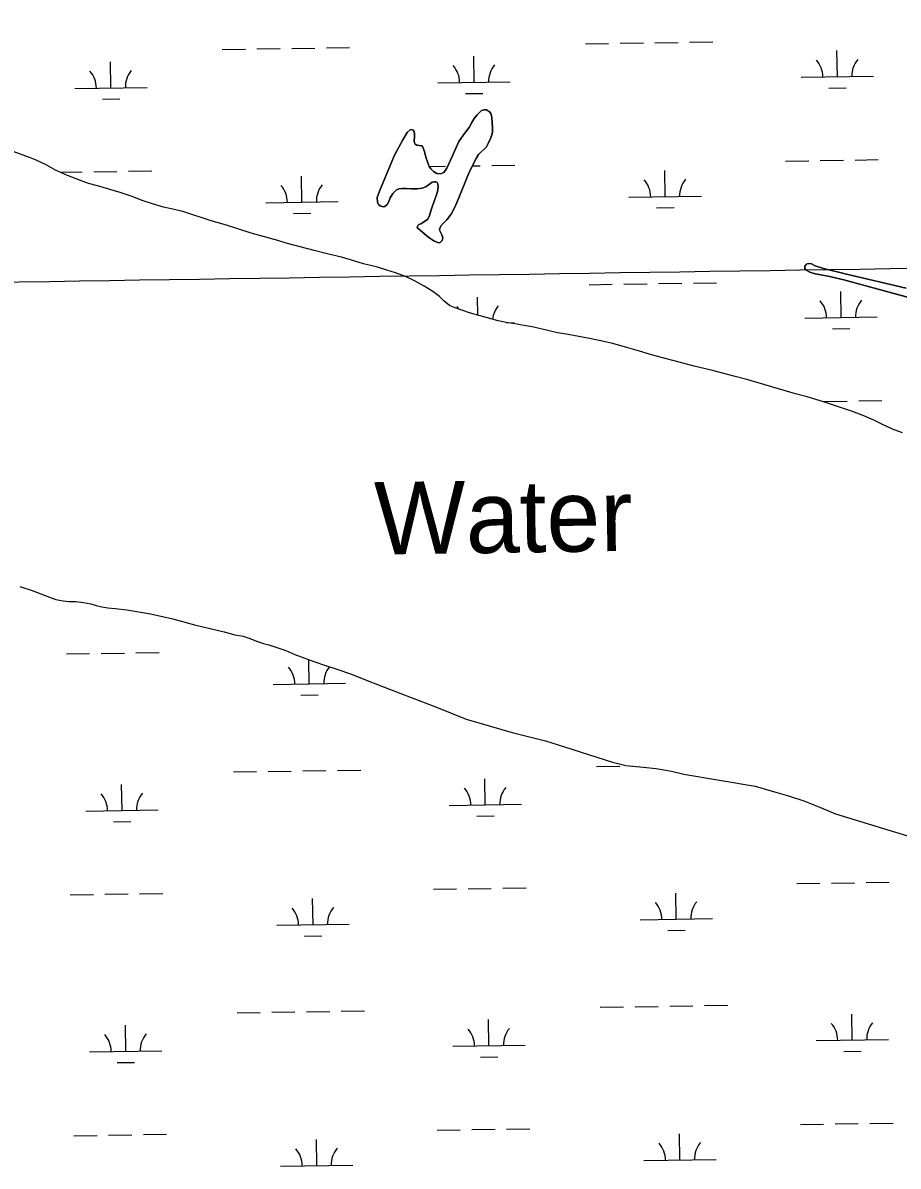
# Model space of a CAD drawing. Extents: x 3823584 to 3861785, y 301729 to 327625.
# Drawn here: x 3836481 to 3837691, y 318188 to 319767 of the extents above; entities that cross this region are included whole.
import ezdxf

# ---------------------------------------------------------------- set-up
doc = ezdxf.new("R2010")
doc.units = 0
for name, color, linetype in [('V-GRID-MAJR', 7, 'Continuous'), ('V-RIVR-IDEN', 7, 'Continuous'), ('V-TOPO-SHOR', 7, 'Continuous'), ('V-WETL-SWMP', 7, 'Continuous')]:
    doc.layers.add(name, color=color, linetype=linetype)

msp = doc.modelspace()

# ---------------------------------------------------------------- linework, layer by layer
at = {"layer": 'V-GRID-MAJR'}
msp.add_spline([(3827642.978, 319275.864), (3832951.406, 319355.783), (3838259.823, 319436.473), (3843568.228, 319517.936), (3848876.6210000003, 319600.17), (3854185.002, 319683.177), (3859493.3710000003, 319766.956), (3859493.372, 319766.956)], degree=3, dxfattribs=at)
at = {"layer": 'V-TOPO-SHOR'}
for points in [[(3837096.325, 319556.064), (3837083.596, 319525.401), (3837078.384, 319512.288), (3837073.092, 319502.832), (3837067.018, 319494.96), (3837059.364, 319487.098), (3837057.466, 319483.553), (3837057.054, 319480.886), (3837058.129, 319478.607), (3837060.4760000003, 319474.244), (3837061.441, 319470.18700000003), (3837060.728, 319466.435), (3837058.142, 319463.48600000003), (3837055.768, 319463.105), (3837049.36, 319465.907), (3837042.173, 319470.59500000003), (3837034.207, 319477.261), (3837027.323, 319483.329), (3837026.342, 319484.718), (3837027.444, 319487.38), (3837028.6380000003, 319488.658), (3837031.114, 319489.631), (3837034.881, 319491.587), (3837040.836, 319496), (3837043.234, 319500.729), (3837045.454, 319508.62200000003), (3837047.463, 319514.244), (3837053.3880000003, 319530.913), (3837054.701, 319535.944), (3837055.127, 319541.179), (3837054.75, 319544.444), (3837053.8740000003, 319546.424), (3837052.002, 319547.62), (3837049.7290000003, 319547.634), (3837046.759, 319546.762), (3837043.286, 319544.014), (3837038.323, 319540.684), (3837032.878, 319538.738), (3837026.054, 319537.689), (3837018.544, 319537.732), (3837011.529, 319538.169), (3837005.895, 319538.3), (3837001.052, 319537.833), (3836996.988, 319535.879), (3836992.417, 319531.359), (3836989.022, 319525.35000000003), (3836987.115, 319520.42100000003), (3836984.721, 319516.284), (3836981.739, 319513.435), (3836979.068, 319513.054), (3836975.1240000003, 319514.363), (3836972.761, 319515.956), (3836971.296, 319519.126), (3836971.038, 319525.94800000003), (3836974.9560000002, 319536.79600000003), (3836995.092, 319584.412), (3837006.2800000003, 319605.398), (3837012.467, 319615.741), (3837016.539, 319619.175), (3837018.419, 319619.462), (3837020.786, 319618.954), (3837021.767, 319617.563), (3837022.636, 319614.002), (3837022.5130000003, 319609.752), (3837022.185, 319604.221), (3837022.365, 319601.255), (3837023.541, 319599.369), (3837025.708, 319598.271), (3837029.0640000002, 319597.757), (3837032.6180000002, 319596.946), (3837034.19, 319595.259), (3837036.328, 319589.217), (3837037.967, 319581.697), (3837042.929, 319568.426), (3837045.282, 319565.151), (3837048.92, 319561.57300000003), (3837053.5500000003, 319559.077), (3837058.586, 319558.552), (3837063.145, 319560.406), (3837067.0300000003, 319566.114), (3837074.733, 319582.377), (3837083.9420000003, 319603.076), (3837089.128, 319610.854), (3837093.1070000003, 319615.87200000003), (3837097.99, 319622.663), (3837101.883, 319629.559), (3837105.076, 319634.777), (3837108.86, 319639.895), (3837115.1210000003, 319645.98600000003), (3837118.98, 319646.854), (3837121.7460000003, 319646.737), (3837125.9820000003, 319644.14400000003), (3837127.845, 319641.95900000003), (3837129.4, 319636.911), (3837129.85, 319629.397), (3837130.1, 319621.59), (3837130.274, 319617.142), (3837129.758, 319613.586), (3837128.048, 319608.063), (3837124.446, 319600.27400000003), (3837121.753, 319595.943)], [(3837121.753, 319595.943), (3837118.5700000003, 319592.404), (3837114.398, 319588.869), (3837111.117, 319585.232), (3837108.324, 319580.701), (3837100.3310000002, 319565.43), (3837096.325, 319556.064)], [(3836996.179, 319421.957), (3836984.342, 319425.58400000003), (3836971.223, 319429.512), (3836952.176, 319434.364), (3836938.561, 319438.39400000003), (3836921.4930000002, 319443.23600000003), (3836901.953, 319447.794), (3836883.994, 319452.443), (3836845.119, 319462.84500000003), (3836833.576, 319466.272), (3836815.224, 319471.318), (3836796.872, 319476.362), (3836778.227, 319482.301), (3836762.941, 319487.427), (3836741.433, 319493.58), (3836702.568, 319506.253), (3836692.899, 319508.78), (3836675.923, 319512.534), (3836660.3340000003, 319516.97000000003), (3836647.413, 319521.391), (3836631.046, 319527.515), (3836615.757, 319532.739), (3836584.4820000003, 319541.714), (3836571.953, 319545.244), (3836560.9080000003, 319549.261), (3836543.258, 319556.181), (3836526.3030000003, 319563.59), (3836513.4990000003, 319570.978), (3836499.798, 319577.183), (3836490.629, 319580.99), (3836467.947, 319589.322)], [(3837696.847, 319200.935), (3837682.843, 319205.954), (3837669.242, 319212.358), (3837657.219, 319218.058), (3837643.517, 319224.067), (3837627.74, 319230.088), (3837587.597, 319243.56), (3837564.807, 319250.31), (3837548.9220000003, 319254.75), (3837481.441, 319274.505), (3837461.8030000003, 319279.36100000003), (3837436.051, 319286.424), (3837409.11, 319292.806), (3837350.105, 319308.559), (3837333.432, 319313.49700000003), (3837317.251, 319318.136), (3837296.433, 319323.987), (3837277.681, 319328.245), (3837264.3570000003, 319331.087), (3837234.642, 319336.594), (3837220.2290000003, 319339.048), (3837204.733, 319342.398), (3837185.194, 319347.055), (3837171.472, 319349.605), (3837161.105, 319351.344), (3837149.157, 319352.995), (3837137.9050000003, 319355.626), (3837113.438, 319362.29), (3837100.019, 319366.221), (3837087.887, 319370.044), (3837080.096, 319372.856), (3837074.771, 319374.863), (3837070.63, 319376.665), (3837063.548, 319382.537), (3837057.163, 319389.097), (3837047.715, 319395.869), (3837035.997, 319403.25), (3837023.488, 319410.339), (3837010.083, 319416.64), (3836996.179, 319421.957)], [(3837712.136, 319385.742), (3837645.83, 319403.711), (3837615.8370000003, 319412.284), (3837593.827, 319417.054), (3837576.157, 319420.319), (3837568.661, 319422.831), (3837563.8340000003, 319425.33), (3837561.968, 319427.51300000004), (3837561.886, 319430.776), (3837564.1780000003, 319433.925), (3837566.1580000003, 319434.505), (3837570.998, 319434.083), (3837576.122, 319431.288), (3837587.662, 319427.564), (3837619.437, 319419.87200000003), (3837701.646, 319400.33)], [(3836477.356, 318988.53), (3836494.123, 318982.999), (3836518.2830000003, 318973.869), (3836527.061, 318970.754), (3836536.932, 318968.821), (3836544.534, 318967.887), (3836554.514, 318967.63300000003), (3836565.082, 318966.48600000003), (3836575.25, 318964.45), (3836582.846, 318962.33), (3836590.444, 318960.51), (3836598.738, 318959.176), (3836609.1070000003, 318957.931), (3836625.109, 318956.457), (3836657.588, 318950.737), (3836688.578, 318943.93700000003), (3836718.772, 318935.762), (3836759.332, 318926.042), (3836774.33, 318922.003), (3836785.977, 318919.76300000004), (3836796.235, 318916.443), (3836804.419, 318913.13300000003), (3836813.789, 318910.016), (3836821.286, 318907.8), (3836832.532, 318904.376), (3836844.7630000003, 318900.05700000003), (3836857.182, 318894.451), (3836883.3140000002, 318884.816), (3836899.688, 318879.384), (3836915.1750000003, 318874.354), (3836935.295, 318867.52), (3836956.887, 318858.8), (3837002.344, 318841.443), (3837052.7290000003, 318821.686)], [(3837052.7290000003, 318821.686), (3837094.096, 318805.12), (3837157.324, 318786.919), (3837203.343, 318775.434), (3837229.541, 318767.211), (3837295.964, 318745.871), (3837314.4760000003, 318741.28), (3837338.2490000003, 318738.842), (3837356.21, 318737.147), (3837377.353, 318733.368), (3837394.804, 318729.559), (3837493.123, 318712.712), (3837523.017, 318703.994), (3837539.42, 318699.382), (3837560.328, 318692.435), (3837583.364, 318683.393), (3837604.288, 318674.597), (3837703.512, 318644.299)]]:
    msp.add_lwpolyline(points, dxfattribs=at)
at = {"layer": 'V-WETL-SWMP'}
for p, q in [((3837258.679514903, 319737.9917449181), (3837290.675711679, 319738.48508539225)), ((3837306.673810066, 319738.73175562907), (3837338.670006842, 319739.22509610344)), ((3837354.6681052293, 319739.4717663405), (3837386.664302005, 319739.96510681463)), ((3837402.662400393, 319740.2117770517), (3837434.658597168, 319740.70511752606)), ((3836756.8311670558, 319730.2538845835), (3836788.827363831, 319730.7472250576)), ((3836804.8254622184, 319730.99389529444), (3836836.8216589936, 319731.4872357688)), ((3836852.8197573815, 319731.73390600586), (3836884.815954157, 319732.22724648)), ((3836900.8140525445, 319732.47391671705), (3836932.81024932, 319732.9672571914)), ((3837104.8881740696, 319684.8724536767), (3837104.3331646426, 319720.8681708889)), ((3837606.736521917, 319692.61031401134), (3837606.18151249, 319728.60603122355)), ((3836603.0398262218, 319677.1345933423), (3836602.4848167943, 319713.1303105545)), ((3837556.742464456, 319691.83946952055), (3837656.7305793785, 319693.38115850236)), ((3836553.0457687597, 319676.3637488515), (3836653.0338836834, 319677.90543783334)), ((3837054.894116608, 319684.1016091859), (3837154.882231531, 319685.64329816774)), ((3837594.97584675, 319676.9961471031), (3837618.9729943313, 319677.36615245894)), ((3836591.2791510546, 319661.52042643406), (3836615.2762986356, 319661.89043178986)), ((3837093.1274989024, 319669.25828676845), (3837117.1246464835, 319669.62829212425)), ((3837042.912999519, 319568.47116892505), (3837065.2647023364, 319568.81580362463)), ((3837102.402600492, 319569.3884225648), (3837113.2589974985, 319569.5558143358)), ((3837129.2570958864, 319569.80248457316), (3837161.2532926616, 319570.295825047)), ((3837368.7885170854, 319527.0602398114), (3837368.233507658, 319563.05595702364)), ((3837535.116853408, 319576.0603234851), (3837567.1130501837, 319576.55366395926)), ((3837583.111148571, 319576.8003341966), (3837615.1073453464, 319577.29367467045)), ((3837631.105443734, 319577.5403449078), (3837663.10164051, 319578.03368538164)), ((3836533.1215502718, 319560.6108361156), (3836563.4163544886, 319561.07794329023)), ((3836579.4144528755, 319561.32461352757), (3836611.4106496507, 319561.8179540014)), ((3836627.4087480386, 319562.06462423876), (3836659.404944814, 319562.5579647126)), ((3836866.940169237, 319519.3223794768), (3836866.38515981, 319555.318096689)), ((3836816.946111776, 319518.5515349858), (3836916.934226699, 319520.0932239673)), ((3837318.7944596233, 319526.2893953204), (3837418.7825745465, 319527.8310843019)), ((3836855.1794940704, 319503.7082125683), (3836879.176641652, 319504.0782179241)), ((3837357.027841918, 319511.44607290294), (3837381.0249894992, 319511.81607825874)), ((3837263.808341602, 319405.356322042), (3837295.8045383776, 319405.84966251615)), ((3837311.8026367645, 319406.09633275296), (3837343.79883354, 319406.58967322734)), ((3837359.7969319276, 319406.8363434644), (3837391.7931287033, 319407.32968393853)), ((3837407.791227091, 319407.5763541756), (3837439.7874238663, 319408.06969464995)), ((3837611.8653486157, 319359.97489113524), (3837611.3103391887, 319395.97060834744)), ((3837109.845779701, 319363.3417522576), (3837109.461991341, 319388.2327480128)), ((3837561.871291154, 319359.20404664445), (3837661.8594060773, 319360.7457356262)), ((3837150.1557543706, 319352.85591909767), (3837160.0110582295, 319353.0078752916)), ((3837600.1046734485, 319344.360724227), (3837624.1018210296, 319344.7307295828)), ((3837588.23997527, 319244.16491132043), (3837620.2361720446, 319244.65825179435)), ((3837636.2342704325, 319244.9049220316), (3837668.230467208, 319245.39826250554)), ((3836541.6778111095, 318895.3137570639), (3836573.674007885, 318895.807097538)), ((3836589.672106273, 318896.0537677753), (3836621.6683030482, 318896.5471082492)), ((3836637.666401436, 318896.7937784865), (3836669.6625982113, 318897.2871189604)), ((3836877.197822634, 318854.05153372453), (3836876.685795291, 318887.2596029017)), ((3836827.203765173, 318853.28068923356), (3836927.1918800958, 318854.8223782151)), ((3836865.437147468, 318838.43736681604), (3836889.434295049, 318838.8073721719)), ((3836772.217647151, 318732.3476159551), (3836804.2138439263, 318732.84095642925)), ((3836820.211942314, 318733.08762666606), (3836852.20813909, 318733.58096714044)), ((3836868.2062374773, 318733.8276373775), (3836900.202434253, 318734.32097785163)), ((3836916.2005326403, 318734.5676480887), (3836948.196729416, 318735.06098856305)), ((3837274.065994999, 318740.08547628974), (3837306.0621917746, 318740.5788167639)), ((3836618.426306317, 318679.22832471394), (3836617.87129689, 318715.22404192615)), ((3837120.274654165, 318686.96618504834), (3837119.719644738, 318722.96190226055)), ((3836568.4322488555, 318678.4574802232), (3836668.4203637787, 318679.99916920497)), ((3837070.2805967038, 318686.1953405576), (3837170.2687116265, 318687.73702953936)), ((3836606.6656311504, 318663.6141578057), (3836630.6627787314, 318663.98416316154)), ((3837108.513978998, 318671.3520181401), (3837132.5111265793, 318671.72202349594)), ((3837048.654985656, 318570.4161945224), (3837080.6511824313, 318570.9095349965)), ((3837096.649280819, 318571.1562052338), (3837128.6454775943, 318571.6495457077)), ((3837144.643575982, 318571.896215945), (3837176.6397727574, 318572.38955641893)), ((3837550.503333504, 318578.15405485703), (3837582.499530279, 318578.6473953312)), ((3837598.497628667, 318578.89406556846), (3837630.4938254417, 318579.38740604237)), ((3837646.4919238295, 318579.63407627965), (3837678.4881206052, 318580.12741675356)), ((3836546.8066378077, 318562.678334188), (3836578.8028345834, 318563.1716746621)), ((3836594.8009329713, 318563.41834489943), (3836626.7971297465, 318563.9116853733)), ((3836642.7952281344, 318564.1583556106), (3836674.7914249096, 318564.65169608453)), ((3836882.3266493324, 318521.41611084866), (3836881.7716399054, 318557.41182806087)), ((3837384.1749971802, 318529.1539711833), (3837383.619987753, 318565.1496883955)), ((3836832.3325918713, 318520.6452663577), (3836932.320706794, 318522.1869553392)), ((3837334.180939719, 318528.3831266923), (3837434.169054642, 318529.92481567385)), ((3836870.565974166, 318505.80194394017), (3836894.563121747, 318506.171949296)), ((3837372.4143220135, 318513.5398042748), (3837396.411469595, 318513.90980963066)), ((3836777.3464738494, 318399.71219307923), (3836809.3426706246, 318400.2055335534)), ((3836825.3407690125, 318400.4522037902), (3836857.336965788, 318400.94554426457)), ((3836873.3350641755, 318401.1922145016), (3836905.3312609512, 318401.68555497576)), ((3836921.3293593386, 318401.9322252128), (3836953.3255561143, 318402.4255656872)), ((3837279.194821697, 318407.45005341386), (3837311.191018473, 318407.943393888)), ((3837327.1891168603, 318408.1900641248), (3837359.185313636, 318408.6834045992)), ((3837375.183412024, 318408.93007483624), (3837407.179608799, 318409.4234153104)), ((3837423.177707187, 318409.67008554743), (3837455.1739039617, 318410.1634260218)), ((3837627.2518287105, 318362.0686225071), (3837626.6968192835, 318398.0643397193)), ((3836623.5551330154, 318346.59290183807), (3836623.0001235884, 318382.5886190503)), ((3837125.403480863, 318354.33076217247), (3837124.848471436, 318390.3264793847)), ((3836573.5610755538, 318345.8220573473), (3836673.549190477, 318347.3637463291)), ((3837075.409423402, 318353.5599176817), (3837175.397538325, 318355.1016066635)), ((3837577.2577712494, 318361.29777801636), (3837677.245886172, 318362.8394669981)), ((3837113.6428056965, 318338.7165952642), (3837137.6399532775, 318339.08660062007)), ((3837615.491153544, 318346.45445559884), (3837639.488301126, 318346.8244609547)), ((3836611.7944578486, 318330.9787349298), (3836635.7916054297, 318331.34874028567)), ((3837053.7838123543, 318237.78077164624), (3837085.78000913, 318238.2741121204)), ((3837101.7781075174, 318238.5207823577), (3837133.7743042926, 318239.0141228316)), ((3837149.7724026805, 318239.2607930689), (3837181.7685994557, 318239.75413354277)), ((3837555.632160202, 318245.5186319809), (3837587.6283569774, 318246.011972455)), ((3837603.626455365, 318246.25864269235), (3837635.622652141, 318246.7519831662)), ((3837651.6207505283, 318246.99865340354), (3837683.616947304, 318247.4919938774)), ((3836551.935464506, 318230.04291131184), (3836583.931661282, 318230.536251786)), ((3836599.9297596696, 318230.7829220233), (3836631.925956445, 318231.2762624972)), ((3836647.9240548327, 318231.5229327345), (3836679.920251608, 318232.01627320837)), ((3836887.455476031, 318188.78068797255), (3836886.900466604, 318224.77640518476)), ((3837389.303823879, 318196.5185483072), (3837388.748814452, 318232.5142655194)), ((3836837.4614185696, 318188.00984348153), (3836937.449533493, 318189.55153246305)), ((3837339.3097664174, 318195.74770381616), (3837439.29788134, 318197.28939279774))]:
    msp.add_line(p, q, dxfattribs=at)
for points in [[(3837121.752, 319595.942), (3837124.4450000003, 319600.275), (3837128.048, 319608.06200000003), (3837129.759, 319613.586), (3837130.274, 319617.141), (3837130.1010000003, 319621.589), (3837129.85, 319629.397), (3837129.399, 319636.911), (3837127.846, 319641.96), (3837125.981, 319644.14400000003), (3837121.747, 319646.738), (3837118.98, 319646.853), (3837115.1210000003, 319645.985), (3837108.86, 319639.89400000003), (3837105.076, 319634.777), (3837101.883, 319629.558), (3837097.99, 319622.662), (3837093.108, 319615.871), (3837089.127, 319610.854), (3837083.943, 319603.076), (3837074.733, 319582.376), (3837067.0300000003, 319566.114), (3837063.144, 319560.405), (3837058.5870000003, 319558.553), (3837053.5500000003, 319559.076), (3837048.919, 319561.57300000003), (3837045.2830000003, 319565.151), (3837042.93, 319568.426), (3837037.966, 319581.697), (3837036.329, 319589.217), (3837034.19, 319595.25800000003), (3837032.6180000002, 319596.947), (3837029.065, 319597.75800000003), (3837025.708, 319598.271), (3837023.54, 319599.37), (3837022.365, 319601.255), (3837022.184, 319604.221), (3837022.5130000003, 319609.753), (3837022.636, 319614.002), (3837021.767, 319617.564), (3837020.786, 319618.953), (3837018.418, 319619.461), (3837016.538, 319619.175), (3837012.467, 319615.74), (3837006.2800000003, 319605.39900000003), (3836995.092, 319584.413), (3836974.9560000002, 319536.79600000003), (3836971.039, 319525.94800000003), (3836971.2970000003, 319519.127), (3836972.761, 319515.957), (3836975.1240000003, 319514.362), (3836979.069, 319513.055), (3836981.74, 319513.435), (3836984.721, 319516.284), (3836987.116, 319520.42), (3836989.022, 319525.351), (3836992.417, 319531.36), (3836996.988, 319535.879), (3837001.051, 319537.833), (3837005.896, 319538.299), (3837011.529, 319538.168), (3837018.543, 319537.733), (3837026.0530000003, 319537.69), (3837032.878, 319538.738), (3837038.324, 319540.683), (3837043.285, 319544.014), (3837046.759, 319546.762), (3837049.7290000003, 319547.634), (3837052.002, 319547.621), (3837053.873, 319546.424), (3837054.751, 319544.443), (3837055.128, 319541.18), (3837054.702, 319535.944), (3837053.389, 319530.912), (3837047.463, 319514.244), (3837045.454, 319508.623), (3837043.235, 319500.73), (3837040.836, 319496), (3837034.881, 319491.587), (3837031.115, 319489.632), (3837028.6380000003, 319488.658), (3837027.4450000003, 319487.38), (3837026.343, 319484.718), (3837027.323, 319483.329), (3837034.2060000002, 319477.261), (3837042.173, 319470.594), (3837049.36, 319465.908), (3837055.768, 319463.105), (3837058.142, 319463.48600000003), (3837060.728, 319466.436), (3837061.441, 319470.18700000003), (3837060.4760000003, 319474.245), (3837058.129, 319478.606), (3837057.055, 319480.886), (3837057.466, 319483.552), (3837059.364, 319487.098), (3837067.018, 319494.96), (3837073.092, 319502.832), (3837078.384, 319512.289), (3837083.597, 319525.402), (3837096.324, 319556.064)], [(3837096.324, 319556.064), (3837100.33, 319565.429), (3837108.324, 319580.701), (3837111.117, 319585.231), (3837114.399, 319588.869), (3837118.5700000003, 319592.403), (3837121.752, 319595.942)], [(3837080.096, 319372.857), (3837074.771, 319374.864), (3837070.63, 319376.666), (3837063.549, 319382.537), (3837057.163, 319389.096), (3837047.715, 319395.87), (3837035.997, 319403.25), (3837023.487, 319410.338), (3837010.0840000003, 319416.64), (3836996.18, 319421.957), (3836984.342, 319425.583), (3836971.222, 319429.512), (3836952.177, 319434.364), (3836938.562, 319438.395), (3836921.494, 319443.23600000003), (3836901.953, 319447.795), (3836883.994, 319452.444), (3836845.1180000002, 319462.84500000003), (3836833.576, 319466.271), (3836815.224, 319471.317), (3836796.872, 319476.363), (3836778.228, 319482.301), (3836762.94, 319487.428), (3836741.432, 319493.579), (3836702.569, 319506.253), (3836692.899, 319508.779), (3836675.923, 319512.533), (3836660.335, 319516.97000000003), (3836647.414, 319521.392), (3836631.045, 319527.514), (3836615.757, 319532.74), (3836584.4820000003, 319541.714), (3836571.952, 319545.245), (3836560.907, 319549.261), (3836543.258, 319556.181), (3836526.3030000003, 319563.591), (3836513.498, 319570.977), (3836499.7970000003, 319577.18200000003), (3836490.629, 319580.99), (3836467.947, 319589.322)], [(3837701.645, 319400.329), (3837619.438, 319419.87200000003), (3837587.662, 319427.565), (3837576.1210000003, 319431.287), (3837570.998, 319434.083), (3837566.1580000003, 319434.506), (3837564.1780000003, 319433.925), (3837561.887, 319430.776), (3837561.968, 319427.514), (3837563.833, 319425.329), (3837568.661, 319422.831), (3837576.157, 319420.318), (3837593.827, 319417.054), (3837615.8370000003, 319412.284), (3837645.83, 319403.712), (3837712.1350000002, 319385.742)], [(3837696.847, 319200.934), (3837682.843, 319205.955), (3837669.242, 319212.358), (3837657.218, 319218.059), (3837643.517, 319224.067), (3837627.739, 319230.087), (3837587.596, 319243.559), (3837564.807, 319250.31), (3837548.9220000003, 319254.749), (3837481.441, 319274.505), (3837461.8030000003, 319279.36), (3837436.051, 319286.425), (3837409.109, 319292.805), (3837350.1040000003, 319308.559), (3837333.431, 319313.49700000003), (3837317.251, 319318.135), (3837296.433, 319323.98600000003), (3837277.681, 319328.244), (3837264.3570000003, 319331.087), (3837234.643, 319336.594), (3837220.2290000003, 319339.048), (3837204.733, 319342.398), (3837185.193, 319347.056), (3837171.471, 319349.605), (3837161.105, 319351.344), (3837149.157, 319352.994), (3837137.906, 319355.627), (3837113.437, 319362.29), (3837100.02, 319366.22000000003), (3837087.886, 319370.045), (3837080.096, 319372.857)], [(3836477.355, 318988.53), (3836494.123, 318982.999), (3836518.282, 318973.868), (3836527.06, 318970.754), (3836536.931, 318968.82), (3836544.535, 318967.887), (3836554.514, 318967.632), (3836565.082, 318966.485), (3836575.2490000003, 318964.45), (3836582.846, 318962.331), (3836590.4450000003, 318960.509), (3836598.738, 318959.177), (3836609.1070000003, 318957.93200000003), (3836625.108, 318956.457), (3836657.588, 318950.737), (3836688.579, 318943.938), (3836718.771, 318935.761), (3836759.332, 318926.042), (3836774.329, 318922.003), (3836785.977, 318919.762), (3836796.236, 318916.442), (3836804.419, 318913.134), (3836813.789, 318910.017), (3836821.287, 318907.8), (3836832.5330000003, 318904.376), (3836844.762, 318900.05700000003), (3836857.182, 318894.452), (3836883.315, 318884.815), (3836899.688, 318879.385), (3836915.174, 318874.355), (3836935.295, 318867.52), (3836956.887, 318858.799), (3837002.344, 318841.443), (3837052.7290000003, 318821.686), (3837094.096, 318805.12), (3837157.325, 318786.919), (3837203.343, 318775.435), (3837229.54, 318767.212), (3837295.963, 318745.87200000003), (3837314.4760000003, 318741.279), (3837338.248, 318738.842), (3837356.2090000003, 318737.147), (3837377.3540000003, 318733.368), (3837394.804, 318729.558), (3837493.122, 318712.711), (3837523.017, 318703.993), (3837539.419, 318699.382), (3837560.327, 318692.434), (3837583.364, 318683.393), (3837604.288, 318674.597), (3837703.511, 318644.299)]]:
    msp.add_lwpolyline(points, dxfattribs=at)
for centre, radius, start, end in [((3837049.6444836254, 319684.4955261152), 35.24628790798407, 0.11153774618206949, 41.655196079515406), ((3837160.117224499, 319686.1988746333), 35.24628790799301, 140.11153456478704, 181.65519289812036), ((3837551.4928314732, 319692.2333864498), 35.24628790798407, 0.11153774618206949, 41.655196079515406), ((3837661.965572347, 319693.936734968), 35.24628790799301, 140.11153456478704, 181.65519289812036), ((3836547.7961357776, 319676.7576657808), 35.24628790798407, 0.11153774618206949, 41.655196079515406), ((3836658.2688766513, 319678.4610142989), 35.24628790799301, 140.11153456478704, 181.65519289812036), ((3837313.5448266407, 319526.6833122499), 35.24628790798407, 0.11153774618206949, 41.655196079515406), ((3837424.0175675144, 319528.386660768), 35.24628790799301, 140.11153456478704, 181.65519289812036), ((3836811.6964787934, 319518.94545191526), 35.24628790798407, 0.11153774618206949, 41.655196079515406), ((3836922.169219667, 319520.6488004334), 35.24628790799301, 140.11153456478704, 181.65519289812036), ((3837054.7733103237, 319351.8601032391), 35.24628790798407, 33.69076314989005, 41.65519607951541), ((3837165.246051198, 319353.5634517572), 35.24628790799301, 140.11153456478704, 173.23889188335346), ((3837556.6216581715, 319359.5979635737), 35.24628790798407, 0.11153774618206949, 41.655196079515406), ((3837667.0943990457, 319361.3013120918), 35.24628790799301, 140.11153456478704, 181.65519289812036), ((3836821.95413219, 318853.67460616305), 35.24628790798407, 0.11153774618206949, 41.655196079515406), ((3836932.426873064, 318855.3779546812), 35.24628790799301, 140.85263775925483, 181.65519289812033), ((3837175.503704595, 318688.292606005), 35.24628790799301, 140.11153456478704, 181.65519289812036), ((3836563.1826158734, 318678.8513971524), 35.24628790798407, 0.11153774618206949, 41.655196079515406), ((3836673.6553567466, 318680.5547456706), 35.24628790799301, 140.11153456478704, 181.65519289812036), ((3837065.030963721, 318686.5892574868), 35.24628790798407, 0.11153774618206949, 41.655196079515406), ((3837439.4040476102, 318530.4803921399), 35.24628790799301, 140.11153456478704, 181.65519289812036), ((3836827.0829588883, 318521.0391832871), 35.24628790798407, 0.11153774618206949, 41.655196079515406), ((3836937.5556997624, 318522.7425318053), 35.24628790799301, 140.11153456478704, 181.65519289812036), ((3837328.931306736, 318528.7770436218), 35.24628790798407, 0.11153774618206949, 41.655196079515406), ((3837572.0081382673, 318361.69169494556), 35.24628790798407, 0.11153774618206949, 41.655196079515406), ((3837682.480879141, 318363.39504346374), 35.24628790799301, 140.11153456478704, 181.65519289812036), ((3836568.3114425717, 318346.21597427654), 35.24628790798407, 0.11153774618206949, 41.655196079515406), ((3836678.784183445, 318347.9193227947), 35.24628790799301, 140.11153456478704, 181.65519289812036), ((3837070.1597904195, 318353.95383461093), 35.24628790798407, 0.11153774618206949, 41.655196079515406), ((3837180.632531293, 318355.6571831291), 35.24628790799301, 140.11153456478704, 181.65519289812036), ((3836832.211785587, 318188.403760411), 35.24628790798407, 0.11153774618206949, 41.655196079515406), ((3836942.6845264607, 318190.10710892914), 35.24628790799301, 140.11153456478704, 181.65519289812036), ((3837334.0601334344, 318196.14162074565), 35.24628790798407, 0.11153774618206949, 41.655196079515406), ((3837444.5328743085, 318197.8449692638), 35.24628790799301, 140.11153456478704, 181.65519289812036)]:
    msp.add_arc(centre, radius, start, end, dxfattribs=at)

# ---------------------------------------------------------------- texts
at = {"layer": 'V-RIVR-IDEN'}
msp.add_text('Water', height=99.99980199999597, rotation=0.8425138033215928, dxfattribs=at).set_placement((3836967.676025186, 319032.58390944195))

doc.saveas('drawing.dxf')
